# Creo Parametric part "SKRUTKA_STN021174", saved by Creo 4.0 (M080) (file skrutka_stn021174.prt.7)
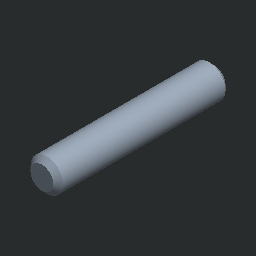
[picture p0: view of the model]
Units: millimeter Kilogram Sec (mmKs); MM, KILOGRAM, SECS
Materials in the file: OCEL_N

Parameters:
  MFG_WP_MATERIAL = "OCEL"
  NAZOV = "SKRUTKA_STN021174"
  NORMA = "STN 02 1174"
  PTC_MATERIAL_NAME = "OCEL_N"

Other parameters: HMOTNOST, HUSTOTA, D24, D13, D20

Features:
  1. datum plane "DTM2"
  2. protrusion
  3. chamfer

Other named items: BLIND, BLIND_1

Layers: 1, 2, 3, 4, 5, 6, 7, 8, 9, 10, 11, 12, 13, 14, 15, 16, 17, 18, 19, 20, 21, 22, 23, 24, 25, 26, 27, 28, 29, 30, 31, 32

Family table entries: GENERIC, SKRUTKA_M3, SKRUTKA_STN021174, value(d_val), value(i_val), SKRUTKA_M4, SKRUTKA_STN021174, SKRUTKA_M5, SKRUTKA_STN021174, SKRUTKA_M6, SKRUTKA_STN021174, SKRUTKA_M8, SKRUTKA_STN021174, !/ , SKRUTKA_M8X1, SKRUTKA_STN021174, !/ , SKRUTKA_M10, SKRUTKA_STN021174, !/$, SKRUTKA_M10X1_25, SKRUTKA_STN021174, !/$, SKRUTKA_M12, SKRUTKA_STN021174, !/(, SKRUTKA_M12X1_25, SKRUTKA_STN021174, !/(, SKRUTKA_M14, SKRUTKA_STN021174, !/,, SKRUTKA_M14X1_5, SKRUTKA_STN021174, !/,, SKRUTKA_M16, SKRUTKA_STN021174, !/0, SKRUTKA_M16X1_5, SKRUTKA_STN021174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

Surfaces: 8 plane, 5 cylinder, 4 cone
